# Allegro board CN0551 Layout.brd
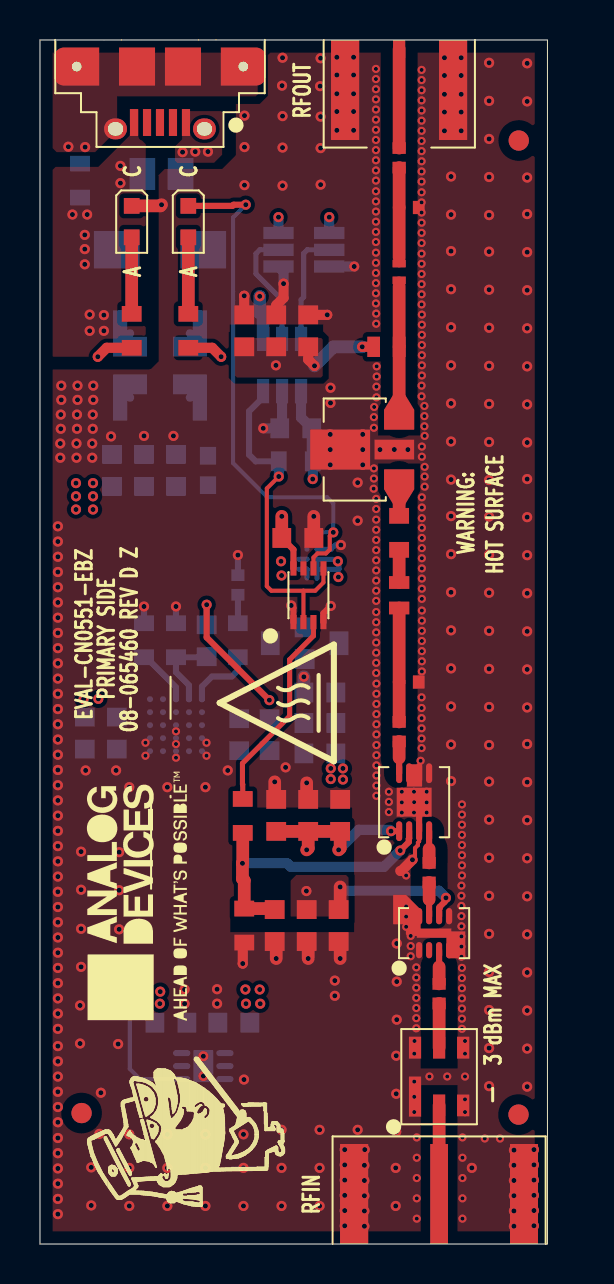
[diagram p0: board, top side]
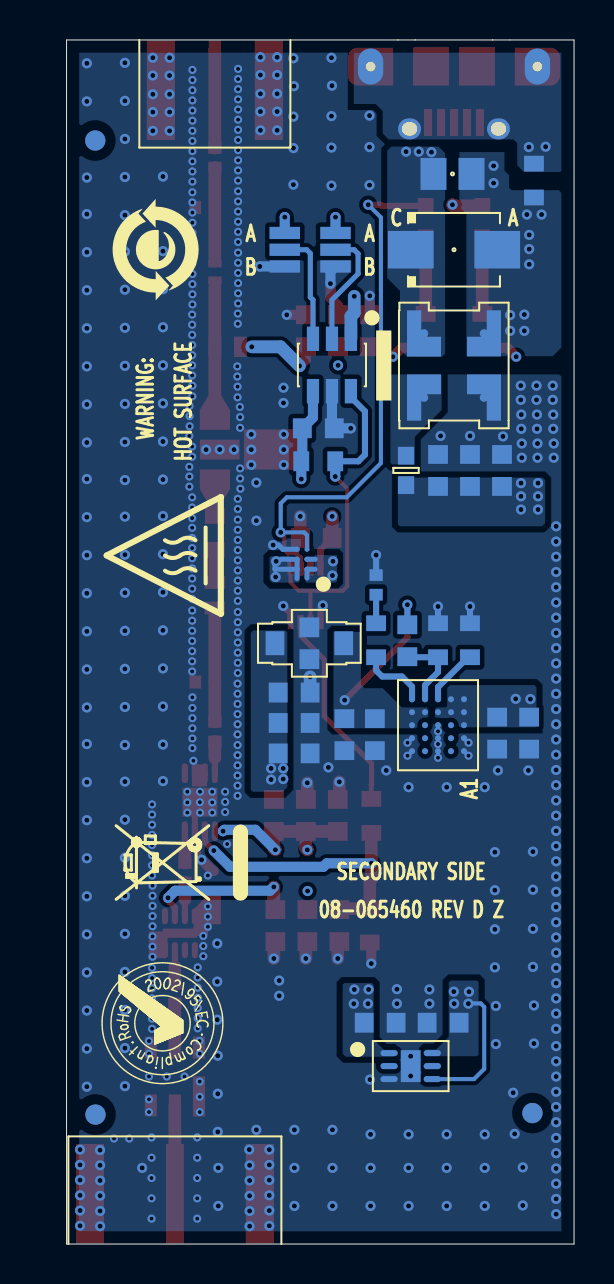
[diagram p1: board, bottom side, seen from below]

Outline 25.4 x 60.25 mm; copper layers: TOP, L2_GND, L3_PWR, BOTTOM. Coordinates in mm from the lower left corner of the outline.
Outline path: 0,60.25 25.4,60.25 25.4,0 0,0 0,60.25

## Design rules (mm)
constraint set DEFAULT: min track width 0.203

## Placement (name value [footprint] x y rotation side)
C1  1000pF  [C0402]  19.98 12.53 90 top
C2  1000pF  [C0402]  19.48 18.58 90 top
C3  100PF  [C0603]  11.75 15.94 270 top
C4  10pF  [C0402]  17.98 25.64 90 top
C5  20PF  [C0402]  18.47 28.12 0 top
C6  6.2pF  [C0402]  18.47 51.87 0 top
C7  20PF  [C0402]  17.98 54.35 90 top
C8  0.47uF  [C0603]  13.35 15.94 270 top
C9  100PF  [C0603]  14.95 15.94 270 top
C10  10uF  [C0603]  11.82 21.45 90 top
C11  100PF  [C0603]  13.42 21.45 90 top
C12  10PF  [C0603]  15.03 21.45 90 top
C13  10uF  [C0603]  10.22 45.69 90 top
C14  0.01UF  [C0603]  11.82 45.69 90 top
C15  100PF  [C0603]  13.42 45.69 90 top
C16  0.1uF  [C0603]  12.8 40.82 180 bottom
C17  0.1uF  [C0603]  12.9 35.33 0 top
C18  47uF  [C0805H60]  6.08 53.55 180 bottom
C19  0.1uF  [C0603]  6.81 38.71 90 bottom
C20  0.1uF  [C0603]  5.21 38.71 90 bottom
C21  0.1uF  [C0603]  3.61 38.71 90 bottom
C22  4.7UF  [C0603]  6.55 11.07 0 bottom
C23  4.7UF  [C0603]  9.7 11.07 180 bottom
C24  22UF  [C0603]  2.25 25.57 270 bottom
C25  22UF  [C0603]  3.85 25.57 270 bottom
C26  22UF  [C0603]  9.97 25.49 270 bottom
C27  22UF  [C0603]  11.49 25.49 270 bottom
C28  47PF  [C0603]  8.34 30.19 270 bottom
C29  27uF  [C1206-4P]  13.25 30.06 0 bottom
C30  10uF  [C0603]  14.01 24.55 180 bottom
C31  10uF  [C0603]  14.01 26.07 180 bottom
C32  10uF  [C0603]  14.01 27.6 180 bottom
C33  2200PF  [C0402]  9.91 32.98 90 bottom
D1  SMAJ5.0A-13-F  [DIOSMJ5_0]  6.01 49.75 180 bottom
E1  120OHM  [L0603]  8.41 38.71 270 bottom
FL1  433.92MEGHZ  [DCC6C]  19.98 8.38 0 top
J1  60314202124525  [CNSMARAL686W374H171]  19.98 0 270 top
J2  60312202114513  [CNSMARAL559W250H131]  17.98 60.25 90 top
JP1  3PIN_SOLDER_JUMPER  [JPRSLD03]  14.48 49.75 270 bottom
JP2  3PIN_SOLDER_JUMPER  [JPRSLD03]  11.94 49.75 270 bottom
L1  1.6NH  [L0603H40]  17.98 32.46 90 top
L2  120NH  [L0603H40]  17.34 44.89 180 top
L3  5.6NH  [L0402-2]  17.98 48.64 90 top
L4  800OHMS AT 100MEGHZ  [L2020_A]  6.01 43.96 270 bottom
NOREF  -  []  -85.24 -81.42 0 top
NOREF#2  -  []  0 6.97 0 top
NOREF#3  -  []  4.89 17.11 90 top
NOREF#4  -  []  194.67 114.19 0 top
NOREF#5  -  []  25.4 53.25 180 top
NOREF#6  -  []  6.97 60.25 270 top
NOREF#7  -  []  20.59 69.75 0 top
NOREF#8  -  []  25.4 0 90 top
NOREF#9  -  []  24.74 -8.8 0 top
NOREF#10  -  []  0 60.25 0 top
NOREF#11  -  []  25.4 0 0 top
NOREF#12  -  []  18.41 0 90 top
NOREF#13  -  []  0 0 0 top
NOREF#14  -  []  -85.24 -81.42 0 top
NOREF#15  -  []  -3.73 90.19 0 top
NOREF#16  -  []  14.73 80.9 0 top
NOREF#17  -  []  -85.24 -81.42 0 top
NOREF#18  -  []  -26.51 208.38 0 top
NOREF#19  -  [unnamed#2]  23.96 55.22 0 top
NOREF#20  -  [unnamed#2]  23.95 6.48 0 top
NOREF#21  -  []  12.64 71.43 0 top
NOREF#22  -  []  0 0 0 top
NOREF#23  -  []  0 60.25 0 top
NOREF#24  -  []  -69.38 316.18 0 top
NOREF#25  -  [unnamed#2]  2.08 6.55 0 top
NOREF#26  -  [unnamed#2]  23.96 55.22 180 bottom
NOREF#27  -  []  3.76 25.43 180 bottom
NOREF#28  -  [unnamed#2]  2.08 6.55 180 bottom
NOREF#29  -  []  3.81 35.56 180 bottom
NOREF#30  -  [unnamed#2]  23.95 6.48 180 bottom
P1  629105150921  [CNWURTH629105150921]  6.01 59.39 180 top
POWER  150060VS55040  [LED0603-2]  4.59 51.16 270 top
R1  10K  [R0603]  10.15 21.42 270 top
R2  10K  [R0603]  10.22 15.94 270 top
R3  2  [R0603]  17.98 35.59 90 top
R4  10K  [R0603]  12.8 39.17 180 bottom
R5  300  [R0603]  7.42 45.69 90 top
R6  1K  [R0603]  2.01 53.22 270 bottom
R7  110K  [R0603]  5.21 30.21 90 bottom
R8  10K  [R0603]  9.91 30.21 90 bottom
R9  15K  [R0603]  6.81 30.21 90 bottom
R10  300  [R0603]  4.59 45.69 90 top
TOVER  150060RS55040  [LED0603-2]  7.42 51.16 270 top
U1  AD8353ACPZ-REEL7  [QFN8_2X3_PAD0_46X1_73]  19.73 15.55 90 top
U2  ADG901BCPZ-500RL7  [DFN8_3X3_PAD1_75X1_45]  18.73 22.11 0 top
U3  ADL5324ARKZ  [SOT-89]  15.75 39.76 90 top
U4  ADT6401SRJZ  [TSOT23_6]  12.12 43.99 0 bottom
U5  NC7WZ125K8X  [US8]  13.44 32.46 0 top
U6  ADP196ACBZ  [WLCSP6]  13.61 34.26 90 bottom
U7  ADM7160ACPZN2.5  [DFN6_2X2_PAD1_6X1]  8.18 8.9 270 bottom
U8  LTM4693IV#PBF  [LGA25_4X3_5_A]  6.81 25.96 90 bottom

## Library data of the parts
C1 C2 = CAP: Tolerance: 10; User Part Number: UPN; alternate symbols: (C0402L); part number: CAP_SM-1000PF,100V,10,E034889,C0402; tolerance: 10
C3 C9 C11 C15 = CAP: User Part Number: UPN; Tolerance: 5; alternate symbols: (C0603L); part number: CAP_SM-100PF,50V,5,E049071,C0603; tolerance: 5
C4 = CAP: Tolerance: 5; User Part Number: UPN; alternate symbols: (C0402L); part number: CAP_SM-10PF,50V,5,E033953,C0402; tolerance: 5
C5 C7 = CAP: Tolerance: 5; User Part Number: UPN; alternate symbols: (C0402L); part number: CAP_SM-20PF,25V,5,E055144,C0402; tolerance: 5
C6 = CAP: Tolerance: 0.25pF; User Part Number: UPN; alternate symbols: (C0402L); part number: CAP_SM-6.2PF,50V,0.25PF,E020872,C0402; tolerance: 0.25pF
C8 = CAP: User Part Number: UPN; Tolerance: 10; alternate symbols: (C0603L); part number: CAP_SM-0.47UF,16V,10,E026592,C0603; tolerance: 10
C10 C13 C30-C32 = CAP: User Part Number: UPN; Tolerance: 20; alternate symbols: (C0603L); part number: CAP_SM-10UF,10V,20,E022682,C0603; tolerance: 20
C12 = CAP: User Part Number: UPN; Tolerance: 5; alternate symbols: (C0603L); part number: CAP_SM-10PF,50V,5,E056627,C0603; tolerance: 5
C14 = CAP: User Part Number: UPN; Tolerance: 10; alternate symbols: (C0603L); part number: CAP_SM-0.01UF,16V,10,E056628,C0603; tolerance: 10
C16 C17 C19-C21 = CAP: User Part Number: UPN; Tolerance: 10; alternate symbols: (C0603L); part number: CAP_SM-0.1UF,16V,10,E026560,C0603; tolerance: 10
C18 = CAP: Tolerance: 20; User Part Number: UPN; alternate symbols: (); part number: CAP_SM-47UF,6.3V,20,E025498,C0805H60; tolerance: 20
C22 C23 = CAP: User Part Number: UPN; Tolerance: 20; alternate symbols: (C0603L); part number: CAP_SM-4.7UF,10V,20,E054276,C0603; tolerance: 20
C24-C27 = CAP: User Part Number: UPN; Tolerance: 20; alternate symbols: (C0603L); part number: CAP_SM-22UF,16V,20,E049658,C0603; tolerance: 20
C28 = CAP: User Part Number: UPN; Tolerance: 5; alternate symbols: (C0603L); part number: CAP_SM-47PF,50V,5,E056629,C0603; tolerance: 5
C29 = CAP4P_V3: User Part Number: UPN; Tolerance: 20; alternate symbols: (); part number: CAP4P_V3_SM-27UF,6.3V,20,E034655,C1206-4P; tolerance: 20
C33 = CAP: Tolerance: 10; User Part Number: UPN; alternate symbols: (C0402L); part number: CAP_SM-2200PF,25V,10,E056630,C0402; tolerance: 10
D1 = DIO: Tolerance: N/A; User Part Number: UPN; alternate symbols: (); part number: DIO_SM-SMAJ5.0A-13-F,5V,N/A,E001108,DIOSMJ5_0; tolerance: N/A
E1 = FERRITE: Tolerance: 25; User Part Number: UPN; alternate symbols: (L0603L); part number: FERRITE_SM-120OHM,25,E012242,L0603; tolerance: 25
FL1 = FLTRSAW6P_V2: Tolerance: N/A; User Part Number: UPN; alternate symbols: (); part number: FLTRSAW6P_V2_SM-433.92MEGHZ,E044551,DCC6C; tolerance: N/A
J1 = CNBNC5P: User Part Number: UPN; Tolerance: N/A; alternate symbols: (); part number: CNBNC5P_SM-60314202124525,E049019,CNSMARAL686W374H171; tolerance: N/A
J2 = CNBNC5P: User Part Number: UPN; Tolerance: N/A; alternate symbols: (); part number: CNBNC5P_SM-60312202114513,E049020,CNSMARAL559W250H131; tolerance: N/A
JP1 JP2 = NC3P_JMPR: Tolerance: N/A; User Part Number: UPN; alternate symbols: (); part number: NC3P_JMPR_SM-3PIN_SOLDER_JUMPER,E005606,JPRSLD03; tolerance: N/A
L1 = IND: Tolerance: 5; User Part Number: UPN; alternate symbols: (); part number: IND_SM-1.6NH,5,E038450,L0603H40; tolerance: 5
L2 = IND: Tolerance: 5; User Part Number: UPN; alternate symbols: (); part number: IND_SM-120NH,5,E055147,L0603H40; tolerance: 5
L3 = IND: Tolerance: 0.2NH; User Part Number: UPN; alternate symbols: (); part number: IND_SM-5.6NH,0.2NH,E055146,L0402-2; tolerance: 0.2NH
L4 = CHOKE4P: User Part Number: UPN; Tolerance: N/A; alternate symbols: (); part number: CHOKE4P_SM-800OHMS AT 100MEGHZ,N/A,E027130,L2020_A; tolerance: N/A
P1 = CN5P_6SHLD: User Part Number: UPN; Tolerance: N/A; alternate symbols: (); part number: CN5P_6SHLD_SM-629105150921,E056633,CNWURTH629105150921; tolerance: N/A
POWER = DIOLED: Tolerance: N/A; User Part Number: UPN; alternate symbols: (); part number: DIOLED_SM-150060VS55040,2.4V,N/A,E056632,LED0603-2; tolerance: N/A
R1 R2 R4 R8 = RES: User Part Number: UPN; Tolerance: 5; alternate symbols: (R0603L); part number: RES_SM-10K,E028377,1/10W,5,R0603; tolerance: 5
R3 = RES: User Part Number: UPN; Tolerance: 1; alternate symbols: (R0603L); part number: RES_SM-2,E031412,1/10W,1,R0603; tolerance: 1
R5 R10 = RES: User Part Number: UPN; Tolerance: 1; alternate symbols: (R0603L); part number: RES_SM-300,E010157,1/10W,1,R0603; tolerance: 1
R6 = RES: User Part Number: UPN; Tolerance: 1; alternate symbols: (R0603L); part number: RES_SM-1K,E029591,1/10W,1,R0603; tolerance: 1
R7 = RES: User Part Number: UPN; Tolerance: 1; alternate symbols: (R0603L); part number: RES_SM-110K,E032492,1/10W,1,R0603; tolerance: 1
R9 = RES: User Part Number: UPN; Tolerance: 1; alternate symbols: (R0603L); part number: RES_SM-15K,E026585,1/10W,1,R0603; tolerance: 1
TOVER = DIOLED: Tolerance: N/A; User Part Number: UPN; alternate symbols: (); part number: DIOLED_SM-150060RS55040,2.4V,N/A,E056631,LED0603-2; tolerance: N/A
U1 = AD8353: alternate symbols: (); part number: AD8353_SM-AD8353ACPZ-REEL7,E006494,QFN8_2X3_PAD0_46X1_73; tolerance: N/A
U2 = ADG901: User Part Number: UPN; Tolerance: N/A; alternate symbols: (); part number: ADG901_SM-ADG901BCPZ-500RL7,E027813,DFN8_3X3_PAD1_75X1_45; tolerance: N/A
U3 = ADL5324: User Part Number: UPN; Tolerance: N/A; alternate symbols: (); part number: ADL5324_SM-ADL5324ARKZ,E016769,SOT-89; tolerance: N/A
U4 = ADT6401: User Part Number: UPN; Tolerance: N/A; alternate symbols: (); part number: ADT6401_SM-ADT6401SRJZ,E038244,TSOT23_6; tolerance: N/A
U5 = NC7WZ125K: Tolerance: N/A; User Part Number: UPN; alternate symbols: (); part number: NC7WZ125K_SM-NC7WZ125K8X,E007008,US8; tolerance: N/A
U6 = ADP196: Tolerance: N/A; User Part Number: UPN; alternate symbols: (); part number: ADP196_SM-ADP196ACBZ,E020438,WLCSP6; tolerance: N/A
U7 = ADM7160_V2: User Part Number: UPN; Tolerance: N/A; alternate symbols: (); part number: ADM7160_V2_SM-ADM7160ACPZN2.5,E018694,DFN6_2X2_PAD1_6X1; tolerance: N/A
U8 = ADLTM4693: Tolerance: N/A; User Part Number: UPN; alternate symbols: (); part number: ADLTM4693_SM-LTM4693IV#PBF,E049026,LGA25_4X3_5_A; tolerance: N/A

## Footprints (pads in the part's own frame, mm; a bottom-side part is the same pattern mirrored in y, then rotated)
C0402
  rect 0.584x0.66 smd: 1(-0.49,0) 2(0.49,0)
C0603
  rect 0.94x0.991 smd: 1(-0.8,0) 2(0.8,0)
C0805H60
  rect 1.295x1.6 smd: 1(-0.953,0) 2(0.953,0)
C1206-4P
  rect 0.94x1.194 smd: 1(-1.72,0) 3(1.72,0)
  rect 0.991x0.991 smd: G1(0,0.795) G2(0,-0.795)
CNSMARAL559W250H131
  rect 0.889x0.61 smd: 1(-0.445,0)
  rect 5.004x1.397 smd: 2(-2.502,2.702) 3(-2.502,-2.702) 4(-2.502,2.702) 5(-2.502,-2.702)
CNSMARAL686W374H171
  rect 5.004x0.889 smd: 1(-2.502,0)
  rect 5.004x1.397 smd: 2(-2.502,4.251) 3(-2.502,-4.251) 4(-2.502,4.251) 5(-2.502,-4.251)
CNWURTH629105150921
  rect 0.406x1.346 smd: 1(-1.3,3.27) 2(-0.65,3.27) 3(0,3.27) 4(0.65,3.27) 5(1.3,3.27)
  oval 1.143x1.041 hole 0.762x0.66: SH1(-2.225,3.59) SH2(2.225,3.59)
  custom 0.476x0.476 hole 1.295x0.762: SH3(-4.175,0.47) SH6(4.175,0.47)
  rect 1.803x1.905 smd: SH4(-1.15,0.47) SH5(1.15,0.47)
DCC6C
  rect 0.61x2.007 smd: 1(-1.205,-1.003)
  rect 0.61x1.092 smd: 2(0,-1.446) 3(1.205,-1.446) 4(1.205,1.446) 5(0,1.446) 6(-1.205,1.446)
DFN6_2X2_PAD1_6X1
  oval 0.305x0.864 smd: 1(-0.65,-1.082) 2(0,-1.082) 3(0.65,-1.082) 4(0.65,1.082) 5(0,1.082) 6(-0.65,1.082)
  rect 1.6x0.991 smd: PAD(0,0)
DFN8_3X3_PAD1_75X1_45
  oval 0.305x0.991 smd: 1(-0.75,-1.45) 2(-0.25,-1.45) 3(0.25,-1.45) 4(0.75,-1.45) 5(0.75,1.45) 6(0.25,1.45) 7(-0.25,1.45) 8(-0.75,1.45)
  rect 1.753x1.448 smd: PAD(0,0)
DIOSMJ5_0
  rect 2.286x1.88 smd: A(2.164,0) C(-2.164,0)
JPRSLD03
  rect 0.61x1.524 smd: 1(-0.838,0) 2(0,0) 3(0.838,0)
L0402-2
  rect 0.381x0.66 smd: 1(-0.419,0) 2(0.419,0)
L0603
  rect 0.889x0.813 smd: 1(-0.737,0) 2(0.737,0)
L0603H40
  rect 0.635x1.016 smd: 1(-0.638,0) 2(0.638,0)
L2020_A
  custom 0.425x0.425 smd: 1(-1.606,-1.501) 2(1.606,-1.501) 3(1.606,1.501) 4(-1.606,1.501)
LED0603-2
  rect 0.787x0.787 smd: A(0.787,0) C(-0.787,0)
LGA25_4X3_5_A
  round 0.305 smd: A1(-1.3,-1.3) A2(-1.3,-0.65) A3(-1.3,0) A4(-1.3,0.65) A5(-1.3,1.3) B1(-0.65,-1.3) B2(-0.65,-0.65) B3(-0.65,0) B4(-0.65,0.65) B5(-0.65,1.3) C1(0,-1.3) C2(0,-0.65) C3(0,0) C4(0,0.65) C5(0,1.3) D1(0.65,-1.3) D2(0.65,-0.65) D3(0.65,0) D4(0.65,0.65) D5(0.65,1.3) E1(1.3,-1.3) E2(1.3,-0.65) E3(1.3,0) E4(1.3,0.65) E5(1.3,1.3)
QFN8_2X3_PAD0_46X1_73
  oval 0.813x0.305 smd: 1(-0.85,0.75) 2(-0.85,0.25) 3(-0.85,-0.25) 4(-0.85,-0.75) 5(0.85,-0.75) 6(0.85,-0.25) 7(0.85,0.25) 8(0.85,0.75)
  rect 0.457x1.727 smd: PAD(0,0)
R0603
  rect 0.787x0.991 smd: 1(-0.85,0) 2(0.85,0)
SOT-89
  rect 0.991x1.499 smd: 1(-1.5,-2.224) 3(1.5,-2.224)
  rect 0.991x1.981 smd: 2(0,-1.983)
  rect 2.007x2.997 smd: 4(0,0.728)
TSOT23_6
  rect 0.61x1.219 smd: 1(-0.95,-1.31) 2(0,-1.31) 3(0.95,-1.31) 4(0.95,1.31) 5(0,1.31) 6(-0.95,1.31)
unnamed#2
  round 1.016 smd: (0,0)
US8
  rect 0.305x0.711 smd: 1(-0.75,-1.343) 2(-0.25,-1.343) 3(0.25,-1.343) 4(0.75,-1.343) 5(0.75,1.343) 6(0.25,1.343) 7(-0.25,1.343) 8(-0.75,1.343)
WLCSP6
  round 0.254 smd: A1(-0.5,-0.25) A2(-0.5,0.25) B1(0,-0.25) B2(0,0.25) C1(0.5,-0.25) C2(0.5,0.25)

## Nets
2V5_POWER: C10.1 C11.1 C12.1 C23.1 U2.1(VDD) U7.1(VOUT)
5V_POWER: C16.1 C17.1 C29.3(OUT) C30.1 C31.1 C32.1 JP1.1 JP2.1 R4.1 R5.1 R10.1 U4.1 U4.4(VCC) U5.8 U6.A1 U6.B1
GND: C3.2(N2) C5.2(N2) C6.2(N2) C8.2(N2) C9.2(N2) C10.2(N2) C11.2(N2) C12.2(N2) C13.2(N2) C14.2(N2) C15.2(N2) C16.2(N2) C17.2(N2) C19.2(N2) C20.2(N2) C21.2(N2) C22.2(N2) C23.2(N2) C24.2(N2) C25.2(N2) C26.2(N2) C27.2(N2) C29.G1 C29.G2 C30.2(N2) C31.2(N2) C32.2(N2) C33.2(N2) FL1.1 FL1.3 FL1.4 FL1.6 J1.2 J1.3 J1.4 J1.5(SH4) J2.2 J2.3 J2.4 J2.5(SH4) JP1.3 JP2.3 L4.3 POWER.C R2.2(N2) R7.2(N2) R9.2(N2) U1.1 U1.4 U1.5 U1.8 U1.PAD U2.3 U2.5 U2.6 U2.7 U2.PAD U3.2 U3.4 U4.5 U5.1 U5.4 U5.7 U6.C2 U7.3 U7.PAD U8.A1 U8.A3 U8.A5 U8.B1 U8.B3 U8.B5 U8.C3
PGND: C18.2(N2) D1.A(P) L4.4(N4) P1.5 R6.2(N2)
ADG901_CTRL: R1.1 U5.3(Y2)
UNNAMED_3_ADP196_I103_EN: TOVER.C U5.6 U6.C1
UNNAMED_3_ADT6401_I86_S0: JP1.2(COM) U4.3
UNNAMED_3_ADT6401_I86_S1: JP2.2(COM) U4.2
UNNAMED_3_ADT6401_I86_TOVERN: R4.2(N2) U4.6 U5.2 U5.5
UNNAMED_3_DIOLED_I93_P: R5.2(N2) TOVER.A(P)
UNNAMED_4_AD8353_I254_RFIN: C1.2(N2) U1.3
UNNAMED_4_AD8353_I254_RFOUT: C2.1 U1.7
UNNAMED_4_ADG901_I260_CTRL: C3.1 R1.2(N2) R2.1 U2.2
UNNAMED_4_ADG901_I260_RF1: C2.2(N2) U2.4
UNNAMED_4_ADG901_I260_RF2: C4.1 U2.8
UNNAMED_4_ADL5324_I250_RFIN: R3.2(N2) U3.1
UNNAMED_4_ADL5324_I250_RFOUT: L2.1 L3.1 U3.3(RFOUT)
UNNAMED_4_CAP_I234_N1: C6.1 C7.1 L3.2(N2)
UNNAMED_4_CAP_I253_N2: C7.2(N2) J2.1
UNNAMED_4_CAP_I256_N1: C4.2(N2) C5.1 L1.1
UNNAMED_4_CAP_I263_N1: C1.1 FL1.5(OUTPUT)
UNNAMED_4_CNBNC5P_I159_CNTR: FL1.2 J1.1
UNNAMED_4_IND_I224_N2: L1.2(N2) R3.1
UNNAMED_5_ADLTM4693_I47_COMP: R8.1 U8.E5
UNNAMED_5_ADLTM4693_I47_FB: C28.2(N2) R9.1 U8.E4
UNNAMED_5_ADLTM4693_I47_FREQ: R7.1 U8.E3
UNNAMED_5_ADLTM4693_I47_VOUT1: C26.1 C27.1 C28.1 C29.1 U8.C5 U8.D4 U8.D5(VOUT_3)
UNNAMED_5_CAP_I25_N1: C18.1 D1.C L4.1 P1.1
UNNAMED_5_CAP_I61_N1: C33.1 R8.2(N2)
UNNAMED_5_CHOKE4P_I23_N2: E1.1 L4.2
UNNAMED_5_CN5P6SHLD_I31_N10: P1.SH1 P1.SH2 P1.SH3 P1.SH4(N9) P1.SH5 P1.SH6 R6.1
UNNAMED_5_DIOLED_I99_P: POWER.A(P) R10.2(N2)
USB_POWER: C19.1 C20.1 C21.1 C22.1 C24.1 C25.1 E1.2(N2) U7.4 U7.6 U8.C1 U8.D1 U8.D2 U8.D3 U8.E1 U8.E2
VBIAS: C8.1 C9.1 C13.1 C14.1 C15.1 L2.2(N2) U1.6(VPOS) U6.A2 U6.B2(VOUT2)

Pads without a net: P1 2 3 4; U1 2; U7 2 5; U8 A2 A4 B2 B4 C2 C4

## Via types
v1: diameter 0.508, hole 0.254, TOP to BOTTOM, 353 vias
v2: diameter 0.406, hole 0.203, TOP to BOTTOM, 214 vias

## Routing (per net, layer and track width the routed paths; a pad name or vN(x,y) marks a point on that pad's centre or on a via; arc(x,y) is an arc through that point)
2V5_POWER: length 8.6
  TOP w0.305: U2.1 v1(17.57,20.66)
  TOP w0.635: C10.1 C11.1 ; C11.1 13.42,19.8 v1(13.35,19.72) ; C11.1 C12.1 15.03,19.8 v1(14.95,19.72)
  BOTTOM w0.508: v1(14.95,19.72) 15.95,20.73 17.5,20.73 v1(17.57,20.66)
  vias: v1(10.28,12.74) v1(10.31,12.03) v1(11,12.74) v1(11.02,12.02)
5V_POWER: length 16.2
  TOP w0.305: C17.1 12.69,34.75 U5.8
  TOP w0.508: v1(2.9,44.4) 3.34,44.84 R10.1 ; R5.1 8.62,44.84 v1(9.07,44.4)
  TOP w0.635: C17.1 v1(12.1,36.41)
  BOTTOM w0.254: U6.B1 12.95,34.26 ; 12.96,33.76 U6.A1 13.36,33.33
  BOTTOM w0.508: JP1.1 v1(14.48,51.38) ; JP2.1 v1(11.94,51.38) ; v1(13.65,38.28) R4.1 13.6,39.22 C16.1 13.07,41.35 U4.4
  BOTTOM w0.635: U4.1 11.17,46.43 11,46.59 v1(11,47.42)
  vias: v1(12.06,34.16) v1(12.09,33.45) v1(14.55,23.8) v1(14.55,23.27) v1(15.16,23.8) v1(15.16,23.24)
GND: length 30.1
  TOP w0.203: U2.3 18.98,20.15 18.92,20.09 18.92,19.96 18.77,19.81 18.77,19.35 v1(18.64,19.23)
  TOP w0.305: v1(14.55,31.93) 14.19,31.56 U5.4 ; U2.7 U2.6 ; v1(12.57,31.95) 12.69,31.84 U5.1 ; U2.3 18.98,21.86 v2(18.73,22.11) 18.48,22.36
  TOP w0.508: v1(10.22,47.45) 10.22,47.45 C13.2 ; v1(12.19,48.06) 12.19,47.35 11.82,46.98 C14.2 ; 10.15,15.14 v1(10.15,14.03) ; C15.2 v1(14.38,46.49) ; 18.03,18.67 18.08,18.67 v1(18.64,19.23)
  TOP w0.635: v1(6.09,52) 6.03,51.95 POWER.C ; 13.42,15.14 v1(13.42,14.29) ; 11.82,15.14 v1(11.82,14.29) ; C17.2 v1(13.7,36.41) ; 15.03,15.14 v1(15.03,14.29) ; 11.75,22.27 v1(11.75,23.13) ; 13.35,22.22 v1(13.35,23.08)
  BOTTOM w0.203: U8.C3 v2(6.81,25.65) ; U8.A5 v2(8.34,24.43) ; U8.B1 v2(5.28,25.08) ; U8.A3 v2(6.81,24.33) ; U8.A1 v2(5.28,24.43) ; U8.B5 v2(8.34,25.08) ; U8.B3 v2(6.81,25.02)
  BOTTOM w0.254: v1(15.06,34.98) 14.78,34.98 14.57,34.76 U6.C2
  BOTTOM w0.305: R9.2 v1(6.81,31.9) ; C33.2 v1(9.91,34.47) ; R7.2 v1(5.21,31.9)
  BOTTOM w0.508: v1(12.19,48.06) 12.19,48.66 JP2.3 ; U4.5 12.12,40.93 C16.2 v1(11.18,40.82) ; JP1.3 v1(15.73,48.91)
  BOTTOM w0.635: C32.2 v1(13.21,28.38)
  vias: v1(0.9,35.91) v1(0.9,35.15) v1(0.9,34.39) v1(0.9,33.63) v1(0.9,32.87) v1(0.9,32.1) v1(0.9,31.34) v1(0.9,30.58) v1(0.9,29.82) v1(0.9,29.06) v1(0.9,28.29) v1(0.9,27.53) v1(0.9,26.77) v1(0.9,26.01) v1(0.9,25.25) v1(0.9,24.48) v1(0.9,23.72) v1(0.9,22.96) v1(0.9,22.2) v1(0.9,21.44) v1(0.9,20.67) v1(0.9,19.91) v1(0.9,19.15) v1(0.9,18.39) v1(0.9,17.63) v1(0.9,16.86) v1(0.9,16.1) v1(0.9,15.34) v1(0.9,14.58) v1(0.9,13.82) v1(0.9,13.05) v1(0.9,12.29) v1(0.9,11.53) v1(0.9,10.77) v1(0.9,9.9) v1(0.9,9.14) v1(0.9,8.38) v1(0.9,7.62) v1(0.9,6.86) v1(0.9,6.09) v1(0.9,5.31) v1(0.9,4.54) v1(0.9,3.78) v1(0.9,3.02) v1(0.9,2.26) v1(0.9,1.5) v1(1.04,41.5) v1(1.04,40.79) v1(1.02,40.06) v1(1.02,39.34) v1(1.07,42.95) v1(1.07,42.24) v1(1.83,40.06) v1(1.83,39.34) v1(1.88,42.95) v1(1.88,42.24) v1(1.85,41.5) v1(1.85,40.79) v1(2.01,11.94) v1(2.01,10.03) v1(2.06,19.63) v1(2.06,17.73) v1(2.06,15.77) v1(2.06,13.87) v1(2.29,23.7) v1(2.64,41.5) v1(2.64,40.79) v1(2.62,40.06) v1(2.62,39.34) v1(2.57,3.84) v1(2.57,1.93) v1(2.67,42.95) v1(2.67,42.24) v1(3.05,7.57) v1(2.97,5.51) v1(3.56,40.41) v1(3.81,23.7) v1(3.91,11.91) v1(3.91,10.01) v1(3.96,19.61) v1(3.96,17.7) v1(3.96,15.75) v1(3.96,13.84) v1(4.47,22.86) v1(4.47,5.49) v1(4.47,3.81) v1(4.47,1.91) v1(5.21,40.44) v1(6.38,22.86) v1(6.38,5.49) v1(6.38,3.81) v1(6.38,1.91) v1(6.68,40.44) v1(7.24,12.74) v1(7.24,12.03) v1(8.18,9.4) v1(8.18,8.41) v1(8.28,22.86) v1(8.28,5.49) v1(8.28,3.81) v1(8.28,1.91) v1(8.86,12.75) v1(8.86,12.03) v1(9.4,23.7) v1(10.24,56.46) v1(10.24,54.89) v1(10.24,52.98) v1(10.21,8.23) v1(10.19,5.49) v1(10.19,3.81) v1(10.19,1.91) v1(12.14,59.36) v1(12.12,57.96) v1(12.14,56.44) v1(12.14,54.86) v1(12.14,52.96) v1(12.09,5.71) v1(12.09,3.81) v1(12.09,1.91) v1(12.29,23.85) v1(14.05,59.33) v1(14.02,57.94) v1(14.05,56.41) v1(14.05,54.84) v1(14.05,53.01) v1(14,5.71) v1(14,3.81) v1(14,1.91) v1(14.54,42.85) v1(14.54,42.09) v1(14.53,40.51) v1(14.53,39.75) v1(14.53,38.99) v1(14.76,13.18) v1(14.76,12.42) v1(14.86,59.39) v1(14.86,58.5) v1(14.86,57.56) v1(14.86,56.67) v1(14.86,55.73) v1(15.25,4.72) v1(15.25,3.96) v1(15.25,3.2) v1(15.25,2.44) v1(15.25,1.67) v1(15.25,0.91) v1(15.7,59.39) v1(15.7,58.5) v1(15.7,57.56) v1(15.7,56.67) v1(15.7,55.73) v1(15.9,38.1) v1(15.9,36.2) v1(15.9,5.71) v1(16.15,40.51) v1(16.15,39.75) v1(16.15,38.99) v1(16.24,3.94) v1(16.24,3.18) v1(16.24,2.42) v1(16.24,1.65) v1(16.24,0.89) v1(16.26,4.72) v1(17.02,39.75) v1(17.74,39.76) v1(17.83,9.42) v1(17.83,7.52) v1(17.83,5.61) v1(17.81,3.81) v1(17.81,1.91) v1(17.86,15.04) v1(17.86,13.13) v1(17.86,11.23) v1(18.41,39.75) v1(20.24,59.36) v1(20.24,58.47) v1(20.24,57.53) v1(20.24,56.64) v1(20.24,55.7) v1(20.57,53.42) v1(20.57,51.51) v1(20.57,49.68) v1(20.57,47.78) v1(20.57,45.87) v1(20.57,43.97) v1(20.57,42.06) v1(20.57,40.16) v1(20.57,38.25) v1(20.57,36.42) v1(20.57,34.52) v1(20.57,32.61) v1(20.57,30.71) v1(20.57,28.8) v1(20.57,26.9) v1(20.57,24.99) v1(20.57,23.16) v1(21.08,59.36) v1(21.08,58.47) v1(21.08,57.53) v1(21.08,56.64) v1(21.08,55.7) v1(21.62,3.81) v1(22.48,59.11) v1(22.48,57.2) v1(22.48,55.3) v1(22.48,53.39) v1(22.48,51.49) v1(22.48,49.66) v1(22.48,47.75) v1(22.48,45.85) v1(22.48,43.94) v1(22.48,42.04) v1(22.48,40.13) v1(22.48,38.23) v1(22.48,36.4) v1(22.48,34.49) v1(22.48,32.59) v1(22.48,30.68) v1(22.48,28.78) v1(22.48,26.87) v1(22.48,24.97) v1(22.48,23.14) v1(22.48,21.23) v1(22.48,19.33) v1(22.48,17.42) v1(22.48,15.52) v1(22.48,13.61) v1(22.48,11.71) v1(22.48,9.8) v1(22.48,7.9) v1(23.72,4.7) v1(23.72,3.94) v1(23.72,3.18) v1(23.72,2.42) v1(23.72,1.66) v1(23.72,0.89) v1(24.38,59.08) v1(24.38,57.18) v1(24.38,53.37) v1(24.38,51.54) v1(24.38,49.63) v1(24.38,47.73) v1(24.38,45.82) v1(24.38,43.92) v1(24.38,42.01) v1(24.38,40.11) v1(24.38,38.28) v1(24.38,36.37) v1(24.38,34.47) v1(24.38,32.56) v1(24.38,30.66) v1(24.38,28.75) v1(24.38,26.85) v1(24.38,25.02) v1(24.38,23.11) v1(24.38,21.21) v1(24.38,19.3) v1(24.38,17.4) v1(24.38,15.49) v1(24.38,13.59) v1(24.38,11.68) v1(24.38,9.78) v1(24.38,7.87) v1(24.72,4.72) v1(24.72,3.96) v1(24.72,3.2) v1(24.72,2.44) v1(24.72,1.68) v1(24.72,0.91) v2(16.73,41.88) v2(16.71,41.38) v2(16.71,40.84) v2(16.71,38.81) v2(16.71,38.3) v2(16.7,37.8) v2(16.81,58.8) v2(16.81,58.29) v2(16.81,57.78) v2(16.81,57.28) v2(16.81,56.77) v2(16.81,56.26) v2(16.81,55.75) v2(16.81,55.24) v2(16.81,54.74) v2(16.81,54.23) v2(16.81,53.72) v2(16.81,53.21) v2(16.81,52.68) v2(16.81,52.17) v2(16.81,51.66) v2(16.81,51.16) v2(16.81,50.65) v2(16.81,50.14) v2(16.81,49.61) v2(16.81,49.1) v2(16.81,48.59) v2(16.81,48.08) v2(16.81,47.57) v2(16.81,47.07) v2(16.83,46.56) v2(16.83,46.05) v2(16.84,42.9) v2(16.84,42.37) v2(16.83,37.29) v2(16.83,36.78) v2(16.83,36.25) v2(16.83,35.74) v2(16.83,35.23) v2(16.83,34.72) v2(16.83,34.21) v2(16.83,33.71) v2(16.83,33.2) v2(16.83,32.69) v2(16.83,32.18) v2(16.83,31.62) v2(16.83,31.11) v2(16.83,30.61) v2(16.83,30.1) v2(16.83,29.59) v2(16.83,29.08) v2(16.83,28.57) v2(16.84,28.04) v2(16.84,27.53) v2(16.84,27.03) v2(16.84,26.52) v2(16.84,26.01) v2(16.84,25.5) v2(16.84,24.97) v2(16.84,24.46) v2(16.84,23.95) v2(16.84,23.44) v2(16.84,22.94) v2(16.84,22.43) v2(16.85,43.92) v2(16.85,43.41) v2(17.36,20.02) v2(17.46,22.63) v2(17.46,22.12) v2(17.46,21.62) v2(18.11,22.63) v2(18.11,22.1) v2(18.11,21.59) v2(18.33,18.44) v2(18.33,16.89) v2(18.33,16.38) v2(18.33,15.88) v2(18.55,15.42) v2(18.55,14.91) v2(18.55,14.4) v2(18.72,22.63) v2(18.72,21.59) v2(18.75,10.16) v2(18.73,9.53) v2(18.73,8.13) v2(18.73,7.37) v2(18.73,6.6) v2(18.83,13.84) v2(18.83,13.34) v2(18.83,12.83) v2(18.83,12.32) v2(18.83,11.81) v2(18.83,11.3) v2(18.83,10.79) v2(18.86,5.33) v2(18.86,4.32) v2(18.86,3.3) v2(18.86,2.29) v2(18.86,1.27) v2(19.1,58.75) v2(19.1,58.24) v2(19.1,57.73) v2(19.1,57.23) v2(19.1,56.72) v2(19.1,56.21) v2(19.1,55.7) v2(19.1,55.19) v2(19.1,54.69) v2(19.1,54.18) v2(19.1,53.67) v2(19.1,53.16) v2(19.1,52.63) v2(19.1,52.12) v2(19.1,51.61) v2(19.1,51.1) v2(19.1,50.6) v2(19.1,50.09) v2(19.1,49.56) v2(19.1,49.05) v2(19.1,48.54) v2(19.1,48.03) v2(19.1,47.52) v2(19.1,47.02) v2(19.11,46.51) v2(19.11,46) v2(19.11,45.49) v2(19.11,44.98) v2(19.11,44.48) v2(19.11,43.97) v2(19.11,43.46) v2(19.1,42.95) v2(19.1,42.42) v2(19.11,39.9) v2(19.11,39.4) v2(19.11,37.36) v2(19.11,36.86) v2(19.11,36.32) v2(19.11,35.84) v2(19.11,35.33) v2(19.11,34.82) v2(19.11,34.32) v2(19.11,33.81) v2(19.11,33.3) v2(19.11,32.79) v2(19.11,32.28) v2(19.11,31.7) v2(19.11,31.19) v2(19.11,30.68) v2(19.11,30.18) v2(19.11,29.67) v2(19.11,29.16) v2(19.11,28.65) v2(19.1,27.36) v2(19.1,26.82) v2(19.1,26.31) v2(19.1,25.81) v2(19.1,25.3) v2(19.1,24.82) v2(19.05,24.18) v2(19.24,41.94) v2(19.24,41.43) v2(19.24,40.92) v2(19.25,40.44) v2(19.25,38.89) v2(19.25,38.4) v2(19.25,37.9) v2(19.35,22.63) v2(19.35,22.1) v2(19.35,21.59) v2(19.49,8.38) v2(20.38,8.38) v2(21.12,22) v2(21.12,21.49) v2(21.12,20.98) v2(21.12,20.47) v2(21.12,19.96) v2(21.12,19.46) v2(21.12,18.95) v2(21.12,18.44) v2(21.09,17.93) v2(21.09,17.42) v2(21.09,16.92) v2(21.09,16.41) v2(21.09,15.9) v2(21.09,15.39) v2(21.09,14.88) v2(21.09,14.38) v2(21.12,13.82) v2(21.12,13.31) v2(21.12,12.8) v2(21.12,12.29) v2(21.12,11.79) v2(21.12,11.28) v2(21.12,10.77) v2(21.15,5.33) v2(21.15,4.32) v2(21.15,3.3) v2(21.15,2.29) v2(21.15,1.27) v2(21.27,10.16) v2(21.27,9.53) v2(21.27,8.38) v2(21.27,7.24) v2(21.27,6.6) v2(22.26,5.28) v2(23.03,5.28)
PGND: length 0.6
  BOTTOM w0.406: C18.2 4.71,53.97
  vias: v1(1.63,51.51) v1(2.24,50.5) v1(2.24,49.78) v1(2.24,49.02) v1(2.36,51.51) v1(2.49,46.51) v1(2.49,45.69) v1(3.2,46.48) v1(3.2,45.69) v1(4.03,53.95) v1(4.03,53.09)
ADG901_CTRL: length 10.3
  TOP w0.254: R1.1 10.15,23 10.13,23.01 10.13,24.05 12.5,26.42 12.5,29.24 13.69,30.43 U5.3
UNNAMED_3_ADP196_I103_EN: length 27.9
  TOP w0.203: v1(14.68,35.61) 14.5,35.43 14.5,34.74 14.32,34.56 13.89,34.56 13.69,34.35 U5.6
  TOP w0.305: TOVER.C 9.63,51.95 9.69,52 v1(10.3,52)
  BOTTOM w0.203: U6.C1 13.36,35.47 13.51,35.61 v1(14.68,35.61) 14.68,37.06 14.38,37.36 11.38,37.36 9.67,39.08 9.67,47.22 9.66,47.22 9.66,47.68 9.67,47.68 9.67,51.37 v1(10.3,52)
UNNAMED_3_ADT6401_I86_S0: length 5.7
  BOTTOM w0.254: U4.3 13.07,47.25 13.2,47.38 13.2,49.57 13.38,49.75 JP1.2
UNNAMED_3_ADT6401_I86_S1: length 6
  BOTTOM w0.254: U4.2 12.12,47.24 10.81,48.55 10.81,49.56 11.01,49.75 JP2.2
UNNAMED_3_ADT6401_I86_TOVERN: length 17
  TOP w0.203: U5.2 13.19,32.68 13.18,32.69 ; 13.18,32.69 13.78,32.69 14.19,33.1 U5.5 ; 13.18,32.69 11.58,32.69 11.35,32.92 11.35,37.81 v1(11.95,38.4)
  BOTTOM w0.305: R4.2 10.79,39.17 10.46,39.5 10.46,41.67 11.17,42.37 U4.6
  BOTTOM w0.508: R4.2 v1(11.95,38.4)
UNNAMED_3_DIOLED_I93_P: length 3.8
  TOP w0.635: TOVER.A R5.2
UNNAMED_4_AD8353_I254_RFIN: length 1.7
  TOP w0.305: 19.98,13.87 U1.3
  TOP w0.635: C1.2 19.98,13.87
UNNAMED_4_AD8353_I254_RFOUT: length 1.7
  TOP w0.305: 19.48,17.24 U1.7
  TOP w0.635: C2.1 19.48,17.24
UNNAMED_4_ADG901_I260_CTRL: length 14.8
  TOP w0.305: U2.2 18.48,20.29 18.46,20.28 18.46,20.12 v1(18.03,19.69)
  TOP w0.635: R1.2 10.15,19.06 v1(10.13,19.05) 10.13,18.28 10.22,18.19 R2.1 11.7,16.79 C3.1
  BOTTOM w0.508: v1(18.03,19.69) 17.22,18.88 12.55,18.88 12.37,19.05 v1(10.13,19.05)
UNNAMED_4_ADG901_I260_RF1: length 1.6
  TOP w0.305: 19.48,19.77 U2.4
  TOP w0.635: C2.2 19.48,19.77
UNNAMED_4_ADG901_I260_RF2: length 1.6
  TOP w0.305: 17.98,24.33 U2.8
  TOP w0.635: C4.1 17.98,24.33
UNNAMED_4_ADL5324_I250_RFIN: length 1.8
  TOP w0.635: R3.2 U3.1
UNNAMED_4_ADL5324_I250_RFOUT: length 7
  TOP w0.381: 17.98,47.92 L3.1
  TOP w0.635: 17.98,47.92 L2.1 U3.3
UNNAMED_4_CAP_I234_N1: length 4.8
  TOP w0.381: 17.98,49.36 L3.2
  TOP w0.635: 17.98,49.36 C6.1 C7.1
UNNAMED_4_CAP_I253_N2: length 5
  TOP w0.635: J2.1 C7.2
UNNAMED_4_CAP_I256_N1: length 5.7
  TOP w0.635: L1.1 C5.1 C4.2
UNNAMED_4_CAP_I263_N1: length 2.2
  TOP w0.635: FL1.5 C1.1
UNNAMED_4_CNBNC5P_I159_CNTR: length 4.4
  TOP w0.635: J1.1 FL1.2
UNNAMED_4_IND_I224_N2: length 1.6
  TOP w0.635: L1.2 R3.1
UNNAMED_5_ADLTM4693_I47_COMP: length 3.4
  BOTTOM w0.305: U8.E5 8.11,27.89 8.61,28.4 9.6,28.4 9.91,28.7 R8.1
UNNAMED_5_ADLTM4693_I47_FB: length 3.9
  BOTTOM w0.305: U8.E4 7.46,27.96 6.81,28.61 R9.1 8.32,29.36 C28.2
UNNAMED_5_ADLTM4693_I47_FREQ: length 2.8
  BOTTOM w0.305: U8.E3 6.81,27.86 5.31,29.36 R7.1
UNNAMED_5_ADLTM4693_I47_VOUT1: length 7.1
  TOP w0.305: v1(11.48,27.22) 8.34,30.35 v1(8.34,31.99)
  BOTTOM w0.305: C28.1 v1(8.34,31.99)
UNNAMED_5_CAP_I25_N1:
  vias: v1(7.14,54.64) v1(7.77,54.66) v1(8.41,54.66)
UNNAMED_5_CAP_I61_N1: length 1.4
  BOTTOM w0.305: C33.1 R8.2
UNNAMED_5_CN5P6SHLD_I31_N10:
  vias: v1(1.42,54.91) v1(2.26,54.89)
UNNAMED_5_DIOLED_I99_P: length 3.8
  TOP w0.635: POWER.A R10.2
USB_POWER: length 6.8
  BOTTOM w0.203: U7.4 5.01,8.25 4.5,8.76 4.5,11.86 4.67,12.04 5.28,12.04 v1(5.29,12.03)
  vias: v1(1.8,38.07) v1(1.8,37.41) v1(1.8,36.75) v1(2.18,27.27) v1(2.66,38.07) v1(2.66,37.41) v1(2.66,36.75) v1(2.92,27.28) v1(5.26,12.62) v1(6.02,12.63) v1(6,12.03)
VBIAS: length 15.4
  TOP w0.305: v1(20.32,17.32) 20.26,17.26 20.26,17.12 19.99,16.86 19.99,16.79 19.98,16.78 U1.6
  TOP w0.508: C15.1 13.42,44.26 v1(13.74,43.94) ; L2.2 v1(16.13,44.89)
  TOP w0.635: 15.03,16.74 v1(15.03,17.87)
  BOTTOM w0.254: U6.A2 13.86,33.3 ; U6.A2 U6.B2 14.64,34.26 ; U6.A2 14.97,33.76 14.97,34.1 v1(14.91,34.16)
  BOTTOM w0.508: v1(15.03,17.87) 15.21,17.68 19.96,17.68 v1(20.32,17.32)
  BOTTOM w0.635: v1(16.13,44.89) 14.69,44.89 v1(13.74,43.94)
  vias: v1(11.81,43.97) v1(13.34,17.66) v1(14.94,33.38)

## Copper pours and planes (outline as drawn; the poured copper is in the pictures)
2V5_POWER on BOTTOM: 9.07,9.7 9.5,9.7 10.03,10.24 10.03,12.98 10.11,13.06 11.51,13.06 11.58,12.98 11.58,9.53 11.43,9.37 9.02,9.37 8.97,9.42 8.97,9.6
2V5_POWER on L3_PWR: 15.37,22.05 15.44,22.05 15.44,19.26 15.26,19.08 11.71,19.08 11.61,19.06 11.53,19 11.12,18.59 11.07,18.51 11.05,18.41 11.05,15.27 11.07,15.17 11.12,15.09 11.3,14.91 11.38,14.85 11.48,14.83 16.13,14.83 16.13,6.81 7.01,6.81 7.01,22.02
5V_POWER on BOTTOM: 12.98,34.47 12.98,33.53 13.44,33.53 13.49,33.48 13.49,33.15 13.44,33.1 11.94,33.1 11.86,33.17 11.86,34.44 11.89,34.47
5V_POWER on BOTTOM: 16.05,30.71 14.45,30.71 14.35,30.61 14.35,22.86 14.58,22.63 16.08,22.63 16.18,22.73 16.18,30.58
5V_POWER on L3_PWR: 5.86,45.04 5.93,45.14 5.96,45.26 5.96,52.09 15.92,52.07 16.13,51.86 16.13,45.72 11.15,45.72 10.97,45.65 10.9,45.47 10.9,43.56 10.92,43.46 10.97,43.38 13.94,40.41 13.94,37.47 13.49,37.01 13.43,36.93 13.41,36.83 13.41,27 13.43,26.9 13.49,26.82 15.44,24.86 15.44,22.56 7.01,22.53 7.01,38.71 6.9,38.98 6.63,39.09 0.64,39.09 0.64,44.56 5.26,44.56 5.38,44.59 5.48,44.66
GND on TOP (solid shape): 19.13,16.66 19.13,16.08 19.05,16 19.05,15.77 19.18,15.65 21.29,15.65 21.29,14.3 20.45,14.3 20.35,14.4 20.35,15.37 20.29,15.42 18.39,15.42 18.31,15.49 18.31,16 17.68,16 17.68,17.48 18.31,17.48
GND on TOP: 18.9,59.61 24.76,59.61 24.76,0.64 0.64,0.64 0.64,43.79 5.56,43.79 5.94,44.17 5.94,53.44 5.92,53.47 6.25,53.8 9.12,53.8 9.8,54.48 9.8,57.05 11,57.05 11.4,57.45 11.4,59.49 11.53,59.61 17.05,59.61 17.05,40.64 18.9,40.64 ; 5 cut-outs
GND on BOTTOM: 9.35,59.61 24.76,59.61 24.76,0.64 0.64,0.64 0.64,43.41 0.74,43.51 9.3,43.51 9.55,43.76 9.55,51.61 9.37,51.79 5.92,51.79 5.44,51.31 5.44,44.37 0.69,44.37 0.64,44.42 0.64,59.61 2.59,59.61 2.59,57.61 4.72,57.61 4.72,59.61 7.31,59.61 7.31,57.61 9.35,57.61
GND on L2_GND: 24.76,59.61 24.76,0.64 0.64,0.64 0.64,43.75 5.36,43.75 5.48,43.78 5.58,43.84 5.84,44.1 5.91,44.2 5.93,44.32 5.93,59.61
GND on L3_PWR: 19.98,59.61 21.37,59.61 21.37,59.61 24.76,59.61 24.76,5 24.99,5 24.99,0.64 23.45,0.64 0.64,0.64 0.64,6.05 16.26,6.05 16.53,6.16 16.64,6.43 16.64,14.83 16.94,14.83 17.04,14.85 17.12,14.91 17.48,15.26 17.53,15.35 17.55,15.44 17.55,44.6 17.53,44.7 17.48,44.78 16.64,45.62 16.64,51.97 16.62,52.07 16.56,52.15 16.21,52.5 16.12,52.56 16.03,52.58 5.96,52.6 5.96,59.44 5.94,59.53 5.9,59.61 14.58,59.61 14.58,59.61 15.98,59.61 15.98,59.61 17.65,59.61 17.65,60.25 18.3,60.25 18.3,59.61 19.98,59.61
PGND on TOP: 5.3,44.46 5.23,44.4 0.66,44.4 0.64,44.42 0.64,45.29 0.64,53.75 0.79,53.9 2.92,53.9 4.5,55.47 4.5,56.79 4.9,56.79 4.93,56.77 4.93,55.4 5.3,55.03
PGND on BOTTOM: 5.74,54.66 5.74,51.89 5.38,51.54 5.38,44.42 1.07,44.42 0.64,44.86 0.64,52.6 0.76,52.73 3.12,52.73 3.25,52.86 3.25,54.64 3.51,54.89 5.51,54.89
PGND on L2_GND: 5.3,59.61 5.3,44.45 5.23,44.39 0.64,44.39 0.64,59.61
PGND on L3_PWR: 5.38,59.61 5.34,59.53 5.32,59.44 5.32,45.39 5.13,45.2 0.64,45.2 0.64,59.61
UNNAMED_4_ADL5324_I250_RFIN on TOP (solid shape): 18.73,37.76 18.25,36.97 17.71,36.97 17.23,37.76 17.23,38.75 18.73,38.75
UNNAMED_4_ADL5324_I250_RFOUT on TOP (solid shape): 18.73,41.75 18.73,40.76 17.23,40.76 17.23,41.75 17.71,42.54 18.25,42.54
UNNAMED_5_ADLTM4693_I47_VOUT1 on BOTTOM: 8.61,26.85 9.58,27.81 10.49,27.81 10.67,27.99 10.67,30.63 12.01,30.63 12.04,30.61 12.04,25.86 11.99,25.81 7.8,25.81 7.29,26.31 7.29,26.77 7.37,26.85
UNNAMED_5_CAP_I25_N1 on TOP: 7.11,56.69 7.11,55.27 6.76,54.91 6.76,54.2 6.86,54.1 8.71,54.1 9.12,54.51 9.12,56.64 9.07,56.69
UNNAMED_5_CAP_I25_N1 on BOTTOM: 6.78,54.91 6.45,54.58 6.45,44.55 6.6,44.4 8.36,44.4 8.71,44.75 8.71,47.7 9.35,48.34 9.35,54.71 9.14,54.91
UNNAMED_5_CHOKE4P_I23_N2 on BOTTOM: 6.63,43.51 9.09,43.51 9.19,43.41 9.19,39.09 9.12,39.01 7.98,39.01 7.98,40.39 6.63,41.73
UNNAMED_5_CN5P6SHLD_I31_N10 on TOP: 0.64,59.61 10.87,59.61 10.9,59.59 10.9,57.53 10.79,57.43 4.11,57.43 4.06,57.38 4.06,55.58 3.12,54.64 0.84,54.64 0.64,54.84
UNNAMED_5_CN5P6SHLD_I31_N10 on BOTTOM: 11.02,59.61 11.02,57.05 9.93,57.05 9.58,56.69 9.58,55.58 9.27,55.27 3.02,55.27 2.84,55.09 2.84,53.98 2.51,53.64 0.69,53.64 0.64,53.7 0.64,59.61
USB_POWER on BOTTOM: 6.96,26.77 6.88,26.85 6.43,26.85 6.35,26.92 6.35,27.84 6.22,27.97 1.98,27.97 1.88,27.86 1.88,25.86 6.27,25.86 6.3,25.88 6.3,26.31 6.88,26.31 6.96,26.39
USB_POWER on BOTTOM: 7.47,9.68 7.47,9.47 7.39,9.4 4.85,9.4 4.78,9.47 4.78,13.11 4.85,13.18 6.17,13.18 6.27,13.08 6.27,10.36 6.91,9.73 7.42,9.73
USB_POWER on BOTTOM: 1.57,38.35 8.81,38.35 8.81,36.02 8.71,35.92 1.6,35.92 1.45,36.07 1.45,38.23
USB_POWER on L3_PWR: 0.64,38.33 6.25,38.33 6.25,6.81 0.64,6.81
VBIAS on TOP: 15.44,16.38 12.55,16.38 12.55,18.19 12.83,18.47 15.32,18.47 15.44,18.34
VBIAS on TOP: 9.75,45.34 14.07,45.34 14.15,45.26 14.15,43.43 14.07,43.36 9.86,43.36 9.75,43.46
VBIAS on BOTTOM: 14.15,34.37 14.15,33.53 13.77,33.53 13.74,33.5 13.74,33.15 13.79,33.1 15.11,33.1 15.24,33.22 15.24,34.34 15.16,34.42 14.2,34.42
VBIAS on L3_PWR: 11.4,45.21 16.33,45.21 17.04,44.5 17.04,15.55 16.84,15.34 11.59,15.34 11.56,15.37 11.56,18.31 11.81,18.57 15.37,18.57 15.46,18.59 15.55,18.64 15.88,18.97 15.93,19.05 15.95,19.15 15.95,24.97 15.93,25.07 15.88,25.15 13.92,27.11 13.92,36.72 14.38,37.18 14.43,37.27 14.45,37.36 14.45,40.51 14.43,40.61 14.38,40.69 11.4,43.67

Small or netless copper shapes (teardrops, artwork), in the pictures only: 1 on TOP

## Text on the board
Ref Des/Assembly Bottom: A | C | 1 | 2 | 3
Ref Des/Silkscreen Bottom: A | 08-065460 REV D Z | SECONDARY SIDE | C | B | HOT SURFACE | WARNING:
User.Comments: SEE NOTE 4 | 4.    PARTS INDICATED BELOW SHOULD BE MOUNTED MANUALLY: | B.    J2, E049020, CONN-PCB EDGE SMA SMALL VERSION, 60312202114513 | A.    J1, E049019, CONN-PCB RCPT PLUG SMA END LAUNCH, 60314202124525
Ref Des/Silkscreen Top: EVAL-CN0551-EBZ | PRIMARY SIDE | 08-065460 REV D Z | C | A | RFOUT | RFIN | WARNING: | 3 dBm MAX | HOT SURFACE
PAGE_OUTLINE: 13OCT20 | B | C | D | CHANGES AS PER ECR-101307 | CHANGES AS PER ECR-103798 | CHANGES AS PER ECR-107133 | 08FEB21 | 05NOV21 | 11MAR22 | A. UY | CUSTOMER EVALUATION | PRIMARY SIDE
DIMENSION: " " | (REF) | DIA MAX | SEE NOTE 14
User.11: A | C | 6.    BOARDS TO BE SHIPPED SINGULATED AFTER ASSEMBLY PROCESS. | 7.    SMOOTHEN EDGES AND FREE FROM BURS AFTER DEPANELIZATION PROCESS.
User.12: 1.    ASSEMBLY VENDOR MUST SOLDER SHORT PINS 1 & 2 OF JP2 AND PIN 2 & 3 OF JP1.
User.15: L3_PWR PLANE    (LAYER 4) | 15.    BOARDS TO BE SHIPPED IN ARRAY | 16.    CLIP BACK THE CENTER PINS OF J1 & J2  BY 5 MILS | 17.    PANELED SOLDER PASTE STENCIL SHOULD BE SENT TO THE CUSTOMER. | 13.5 MILS | 50 OHMS CPWG
User.24: L2 GND | 08-      -07
User.25: L2 GND | 08-      -07
User.26: 08-      -08 | L3 PWR
User.27: L5 GND
User.45: FIGURE | SIZE | 8.0 | 10.0 | 30.0x26.0 | 51.0x30.0 | PLATED | DRILL CHART: TOP to BOTTOM | ALL UNITS ARE IN MILS | QTY | 214 | 353 | 2 | TOLERANCE/NOTES
